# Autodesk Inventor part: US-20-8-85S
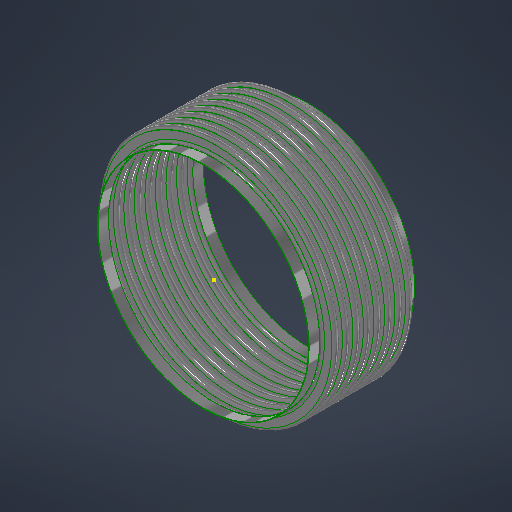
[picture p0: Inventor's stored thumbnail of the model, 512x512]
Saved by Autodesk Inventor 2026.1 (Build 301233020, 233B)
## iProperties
Category: 18 GA (0.048 THICK)
RuleStatus: InUse
Created: 2026-07
Part Number: US-20-8-85S
Project: =STOCK BELLOWS: <Stock Number><SFILL>
Material: ASTM A240-304
Description: =STOCK BELLOWS: <Stock Number>, <SID_> I.D., <SOD_> O.D., <SPLY_> PLY, <Category>, <SNET_CONS> CONS.<PITCH_><STANGENT_> TANGENT<SFILL>
Document SubType Name: Sheet Metal
Designer: LC
Stock Number: U.S-20-8-85S
Surface Area: 659.127 cm^2
Volume: 56.61 cm^3
Sheet Metal Rule: Default
Appearance: STAINLESS STEEL
NET_TUBE: 3.428
COUNTER: 1.500
PBAR: 1.214
PSET: 5.356
PLY: 2
CONS: 2
THK: 0.036
ID: 4.500
OD: 5.500
CONS_: 2
TANGENT: 0.500
PITCH: 0.375
BELLOWS_UPSET: 0.000
NET_CONS: 2
S_CONS: 0
Description_Units: 0
ID_M: 114.30 mm
OD_M: 139.70 mm
THK_M: 0.91 mm
ID_U: 4.500 in
OD_U: 5.500 in
THK_U: 0.036 in
TANGENT2: 0.500
d79: 1.000
d82: 1.000
d83: 26.000
d84: 24.000
d80: 2.571
d81: 10
SID: 2.375
SCONS_: 8
SPITCH: 0.250
SBELLOWS_UPSET: 0.000
SNET_CONS: 8
SS_CONS: 0
SCONS: 8
d174: 8
d177: 0.018
d178: 2.375
d179: 3.000
d180: 0.375
d181: 1.000
d182: 0.000
d190: 8
d191: 1
d192: 1
d193: 8
d194: 0
PART_NUMBER: U.S-20-8-85S
PRESSURE: 85
SIZE: 20.00
STANGENT_: 1.000
d214: 8
d217: 0.030
d218: 6.625
d219: 8.125
d220: 0.500
d221: 1.000
d222: 0.000
d230: 8
d231: 1
d232: 1
d233: 8
d234: 0
STANGENT: 4.000
SPLY_: 1
STHK_: 0.048
SID_: 20.000
SOD_: 22.500
SPITCH_: 1.000
STANGENT__: 1.000
SBELLOWS_UPSET_: 0.000
SDIFF_TAN: 1.000
TAN_TO_TAN: 0.750 in
d252: 2
d275: 2
d287: 0.050
d289: 0.500
d290: 0.000
d263: 2
d265: 1
d268: 2
d269: 0
d286: 2
d288: 1
d291: 2
d292: 0
SOD_NECK: 20 1/8
CFILL: .
SFILL: .
PITCH_: =, <SPITCH_> PITCH,
SREROLL: 0.750
MATTABLE: 20 GA (0.036 THICK)
MESH: ,
CSECT: 2
Author: LC
Keywords: 20 GA (0.036 THICK)
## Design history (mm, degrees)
sketch "Sketch2"
  geometry: L1 (0, -183.595)-(0, 600.956) reference; L2 (58.979, 0)-(57.15, 0); L3 (60.446, -1.467)-(66.554, -1.467); L4 (60.446, -3.296)-(66.554, -3.296); L5 (66.554, -8.058)-(60.446, -8.058); L6 (66.554, -6.229)-(60.446, -6.229); L7 (58.979, -9.525)-(57.15, -9.525); L8 (60.446, 0)-(60.446, -9.525); L9 (66.554, -4.762)-(69.85, -4.763); L10 (57.15, 0)-(57.15, -9.525); L11 (20.376, 102.841)-(20.376, 101.926); L12 (58.262, 488.877)-(58.262, 349.177); L13 (58.262, 479.352)-(58.262, 339.652); L14 (93.133, -58.817)-(93.133, -71.517); L15 (118.746, -66.401)-(118.746, -66.401); L16 (66.554, -6.229)-(66.554, -8.058); L17 (60.446, -6.229)-(60.446, -8.058); L18 (60.446, -7.144)-(66.554, -7.144); L19 (69.85, 0)-(69.85, -9.525); L20 (-66.554, -6.229)-(-66.554, -8.058); L21 (-66.554, -1.467)-(-60.446, -1.467); L22 (-66.554, -3.296)-(-60.446, -3.296); L23 (-60.446, -6.229)-(-66.554, -6.229); L24 (-66.554, -7.144)-(-60.446, -7.144); L25 (-60.446, -8.058)-(-66.554, -8.058); L26 (-60.446, -6.229)-(-60.446, -8.058); L27 (-57.15, -2.522)-(-57.15, -12.047); L28 (-60.446, -4.763)-(-57.15, -4.763); L29 (-66.554, 3.828)-(-66.554, -9.525); L30 (-68.021, 0)-(-69.85, 0); L31 (-69.85, 0)-(-69.85, -9.525); L32 (-68.021, -9.525)-(-69.85, -9.525); A1 r 1.467 centre (60.446, 0) between (58.979, 0) and (60.446, -1.467); A2 r 3.296 centre (60.446, 0) between (57.15, 0) and (60.446, -3.296); A3 r 3.296 centre (66.554, -4.762) between (66.554, -8.058) and (66.554, -1.467); A4 r 1.467 centre (66.554, -4.762) between (66.554, -6.229) and (66.554, -3.296); A5 r 1.467 centre (60.446, -9.525) between (60.446, -8.058) and (58.979, -9.525); A6 r 3.296 centre (60.446, -9.525) between (60.446, -6.229) and (57.15, -9.525); A7 r 2.381 centre (66.554, -4.762) between (66.554, -7.144) and (68.936, -4.762); A8 r 2.381 centre (60.446, -9.525) between (60.446, -7.144) and (58.064, -9.525); A9 r 1.467 centre (-66.554, -9.525) between (-66.554, -8.058) and (-68.021, -9.525); A10 r 1.467 centre (-60.446, -4.763) between (-60.446, -6.229) and (-60.446, -3.296); A11 r 2.381 centre (-60.446, -4.763) between (-60.446, -7.144) and (-58.064, -4.763); A12 r 3.296 centre (-60.446, -4.763) between (-60.446, -8.058) and (-60.446, -1.467); A13 r 2.381 centre (-66.554, -9.525) between (-66.554, -7.144) and (-68.936, -9.525); A14 r 3.296 centre (-66.554, -9.525) between (-66.554, -6.229) and (-69.85, -9.525); A15 r 1.467 centre (-66.554, 0) between (-68.021, 0) and (-66.554, -1.467); A16 r 3.296 centre (-66.554, 0) between (-69.85, 0) and (-66.554, -3.296); 10 further points
  constraints: 62 end point, 38 point on circle, 20 tangent, 16 centre point, 12 parallel, 9 midpoint, 7 vertical, 6 coincident, 6 concentric, 6 point on line, 4 equal radius, 4 perpendicular, 3 horizontal, 1 collinear, 1 horizontal alignment, 10 other
  dimensions: "THK" = 0.9144 distance of L11.start L11.end; "ID" = 114.3 distance of L11.end point (20.376, -12.374); "OD" = 139.7 distance of L12.start L12.end; "PITCH" = 9.525 distance of L12.start L13.start; "TANGENT" = 12.7 distance of L14.start L14.end; "BELLOWS_UPSET" = 0 distance of L15.start L15.end; "d43" = 114.3 diameter of L10 L1 (= ID); "d44" = 139.7 diameter of L9.end L1 (= OD); "d45" = 1.8288 distance between parallel lines of L5 L6 (computed from THK, PLY); "d46" = 3.29565 radius of A3 (computed from PITCH, THK, PLY); "UPSET_PITCH" = 9.525 distance of L2.end L7.end (derived); "SIDEWALL_ANGLE" = 0 deg angle of L3 L9 (derived); "CON_GAP" = 2.9337 distance of point (60.446, -6.229) point (60.446, -3.296) (derived); "TAN1" = 3.74046 dimension on A8 (derived); "TAN2" = 3.74046 dimension on A7 (derived); "LEG1" = 6.1087 distance of L18.start L18.end (derived); "d278" = 1.8288 distance between parallel lines of L25 L23 (derived); "d279" = 3.29565 radius of A12 (derived); "d280" = 9.525 distance of L30.end L31.end (derived); "d281" = 360 deg dimension on L21 L28 (derived); "d282" = 2.9337 distance of point (-66.554, -6.229) point (-66.554, -3.296) (derived); "d283" = 3.74046 dimension on A13 (derived); "d284" = 3.74046 dimension on A11 (derived); "d285" = 6.1087 distance of L24.start L24.end (derived); "d293" = 114.3 diameter of L27 L1 (derived); "d294" = 139.7 diameter of L31 L1 (derived)
  node "Sketch Rectangular Pattern1" dims "d31" = 25.4, "ID" = 114.3
  node "Sketch Rectangular Pattern2" dims "d39" = 25.4, "PITCH" = 9.525
revolve "CONS" stored, may be unused: angle "d48" = 90 deg
node "BELLOW MIDPLANE"
pattern_linear "Rectangular Pattern2" dims "d52" = 9.525 (= UPSET_PITCH)
sketch "Sketch5"
  geometry: C1 r 58.979 at (0, 0) reference; C2 r 57.15 at (0, 0) reference
extrude "TANGENT" new body sketch "Sketch5" distance "d53" = 12.7 (= TANGENT); taper "d54" = 0 deg
revolve "SAMETAN" stored, may be unused: angle "d65" = 90 deg
revolve "DIFFTAN" stored, may be unused: angle "d70" = 90 deg
sketch "Sketch9"
  geometry: L1 (58.391, 0)-(-58.391, 0) reference; L2 (0, -17.78)-(0, 17.78) reference; L3 (41.708, 0)-(-41.708, 0); L4 (41.708, -11.906)-(41.708, 11.906); L5 (29.008, -11.906)-(29.008, 11.906); L6 (15.418, 11.906)-(15.418, -11.906); L7 (-29.008, -11.906)-(-29.008, 11.906); L8 (-41.708, -11.906)-(-41.708, 11.906); L9 (40.914, -11.906)-(40.914, 11.906); L10 (41.708, -11.906)-(40.914, -11.906); L11 (41.708, 11.906)-(40.914, 11.906); L12 (15.815, 11.906)-(15.022, 11.906); L13 (15.022, 11.906)-(15.022, -11.906); L14 (15.022, -11.906)-(15.815, -11.906); L15 (15.815, -11.906)-(15.815, 11.906); L16 (-15.815, 11.906)-(-15.815, -11.906); L17 (-15.418, 11.906)-(-15.418, -11.906); L18 (-15.815, -11.906)-(-15.022, -11.906); L19 (-15.022, -11.906)-(-15.022, 11.906); L20 (-15.022, 11.906)-(-15.815, 11.906); L21 (-41.708, -11.906)-(-40.914, -11.906); L22 (-40.914, -11.906)-(-40.914, 11.906); L23 (-40.914, 11.906)-(-41.708, 11.906); L24 (-41.708, 11.906)-(-41.708, -11.906); L25 (41.708, -0.397)-(-41.708, -0.397); L26 (-41.708, -0.397)-(-41.708, 0.397); L27 (-41.708, 0.397)-(41.708, 0.397); L28 (41.708, 0.397)-(41.708, -0.397); L29 (-41.708, 11.906)-(41.708, 11.906); L30 (41.708, 11.906)-(41.708, 12.7); L31 (41.708, 12.7)-(-41.708, 12.7); L32 (-41.708, 12.7)-(-41.708, 11.906); L33 (41.708, -11.906)-(-41.708, -11.906); L34 (-41.708, -11.906)-(-41.708, -12.7); L35 (-41.708, -12.7)-(41.708, -12.7); L36 (41.708, -12.7)-(41.708, -11.906); 30 further points
  constraints: 68 end point, 13 midpoint, 13 parallel, 8 horizontal, 7 perpendicular, 6 equal length, 3 point on line, 2 vertical, 14 other
  dimensions: "d115" = 23.8125 distance of L4.start L4.end (derived); "d116" = 12.7 distance between parallel lines of L4 L5 (derived); "d117" = 13.58962 distance between parallel lines of L5 L6 (derived); "d125" = 44.42645 distance between parallel lines of L7 L6 (derived); "d127" = 12.7 distance between parallel lines of L8 L7 (derived); "d128" = 26.28962 distance between parallel lines of L6 L4 (derived); "d130" = 83.41607 distance between parallel lines of L8 L4 (derived); "RULER_THK" = 0.79375 distance between parallel lines of L4 L9; "d135" = 0.79375 distance of L13.end L14.end (derived); "d138" = 30.83684 distance of L13.end L16.end (derived); "d143" = 0.79375 distance of L22.end L8.end (derived); "d144" = 0.79375 distance between parallel lines of L27 L25 (derived)
extrude "RULER" join sketch "Sketch9" distance "d149" = 0.79375 (derived); taper "d150" = 0 deg
extrude "BARS" join sketch "Sketch9" distance "d151" = 0.79375 (derived); taper "d152" = 0 deg
pattern_linear "Rectangular Pattern4" dims "d155" = 30.83684 (derived)
sketch "Sketch13"
  geometry: L1 (93.149, -52.467)-(93.149, -77.867); L2 (255.219, 0)-(254, 0); L3 (255.219, -25.4)-(254, -25.4); L4 (278.79, -19.66)-(260.96, -19.66); L5 (278.79, -18.44)-(260.96, -18.44); L6 (278.79, -12.7)-(285.75, -12.7); L7 (260.96, -5.74)-(278.79, -5.74); L8 (260.96, 0)-(260.96, -25.4); L9 (254, 0)-(254, -25.4); L10 (58.254, -203.273)-(58.254, -774.773); L11 (58.254, -228.673)-(58.254, -800.173); L12 (58.254, -279.473)-(58.254, -850.973); L13 (58.254, -304.873)-(58.254, -876.373); L14 (58.254, -330.273)-(58.254, -901.773); L15 (58.254, -355.673)-(58.254, -927.173); L16 (58.254, -381.073)-(58.254, -952.573); L17 (58.254, -254.073)-(58.254, -825.573); L18 (20.376, 103.145)-(20.376, 101.926); L19 (260.96, -6.96)-(278.79, -6.96); L20 (0, -1123.076)-(0, 307.516) reference; L21 (-52.07, 0)-(312.42, 0) reference; A1 r 5.74 centre (260.96, 0) between (255.219, 0) and (260.96, -5.74); A2 r 5.74 centre (260.96, -25.4) between (260.96, -19.66) and (255.219, -25.4); A3 r 6.96 centre (260.96, -25.4) between (260.96, -18.44) and (254, -25.4); A4 r 5.74 centre (278.79, -12.7) between (278.79, -18.44) and (278.79, -6.96); A5 r 6.96 centre (278.79, -12.7) between (278.79, -19.66) and (278.79, -5.74); A6 r 6.96 centre (260.96, 0) between (254, 0) and (260.96, -6.96); 6 further points; 1 other entity
  constraints: 38 end point, 15 point on circle, 9 tangent, 6 centre point, 6 parallel, 5 vertical alignment, 4 point on line, 4 vertical, 3 coincident, 3 concentric, 2 collinear, 2 equal radius, 1 horizontal, 1 perpendicular, 23 other
  dimensions: "SBELLOWS_UPSET_" = 0 distance of point (118.762, -66.401) point (118.762, -66.401); "STOTAL_THK_BELLOW__" = 1.2192 distance between parallel lines of L4 L5 (derived); "d224" = 6.9596 radius of A5 (derived); "d225" = 25.4 distance of L2.end L3.end (derived); "SSIDEWALL_ANGLE_" = 0 deg angle of L7 L6 (derived); "SSCON_GAP_" = 11.4808 distance of point (260.96, -18.44) point (260.96, -6.96) (derived); "d235" = 508 diameter of L9 L20 (derived); "d236" = 571.5 diameter of L6.end L20 (derived)
  node "Sketch Rectangular Pattern4" dims "d228" = 25.4
  node "Sketch Rectangular Pattern5" dims "d229" = 25.4
revolve "SBELLOW" stored, may be unused: angle "d197" = 90 deg
pattern_linear "Rectangular Pattern5" dims "d204" = 25.4 (derived)
revolve "STANGENT" stored, may be unused: angle "d240" = 90 deg
revolve "SSAMETAN" stored, may be unused: angle "d241" = 90 deg
revolve "SDIFFTAN" stored, may be unused: angle "d246" = 90 deg
revolve "INVCON" stored, may be unused: angle "d295" = 90 deg
pattern_linear "Rectangular Pattern6" dims "d298" = 9.525 (derived)
revolve "INVTANGENT" stored, may be unused: angle "d302" = 90 deg
revolve "INVSAMETAN" stored, may be unused: angle "d307" = 90 deg
revolve "INVDIFFTAN" stored, may be unused: angle "d312" = 90 deg
sketch "ID BELLOW MOUNT CALC"
  geometry: L1 (44.45, 0)-(38.1, 0); L2 (38.1, 0)-(38.1, 12.7); L3 (38.1, 12.7)-(44.45, 12.7); L4 (44.45, 12.7)-(44.45, 0); L5 (36.513, 12.7)-(34.684, 12.7); L6 (34.684, 12.7)-(34.684, 0); L7 (34.684, 0)-(36.513, 0); L8 (36.513, 0)-(36.513, 12.7); L9 (0, -2.54)-(0, 15.24) reference; L10 (-8.89, 0)-(53.34, 0) reference; 1 further point
  constraints: 16 end point, 5 parallel, 2 collinear, 2 horizontal, 2 perpendicular
  dimensions: "d314" = 12.7 distance of L5.end L6.end (derived); "d315" = 1.8288 distance of L5.start L5.end (derived); "IG" = 1.5875 distance between parallel lines of L2 L8; "PIPE_OD" = 88.9 diameter of L4 L9; "PIPE_WALL" = 6.35 distance of L2.end L3.end; "ID_MT_BELLOW" = 69.3674 diameter of L6 L9 (derived)
revolve "CFILL" stored, may be unused: angle "d320" = 90 deg
pattern_linear "Rectangular Pattern7" dims "d323" = 9.525 (derived)
revolve "SFILL" stored, may be unused: angle "d324" = 90 deg
pattern_linear "Rectangular Pattern8" dims "d327" = 25.4 (derived)
node "STOCK BELLOW MIDPLANE"
sketch "Sketch21"
  geometry: L1 (0, -100.013)-(0, 100.013) reference; L2 (-100.013, 0)-(100.013, 0) reference; L3 (-0.099, 71.437)-(0.099, 71.437); L4 (0.099, 71.437)-(0.099, 55.562); L5 (0.099, 55.562)-(-0.099, 55.562); L6 (-0.099, 55.562)-(-0.099, 71.437); C1 r 55.562 at (0, 0); C2 r 71.437 at (0, 0); 3 further points
  constraints: 8 end point, 2 centre point, 2 coincident, 2 parallel, 2 tangent, 1 horizontal, 1 perpendicular, 1 other
  dimensions: "d329" = 111.125 diameter of C1 (derived); "d330" = 142.875 diameter of C2 (derived); "d331" = 0.19844 distance of L3.start L3.end
extrude "CLAMSHELL" cut sketch "Sketch21" extent not by distance; stored distance "d332" = 0; taper "d333" = 0 deg
pattern_circular "Circular Pattern1" dims angle "d335" = 180 deg (derived)
node "BELLOW"
sketch "Sketch6"
  geometry: L1 (-19.05, 58.979)-(-6.35, 58.979); L2 (-6.35, 58.979)-(-6.35, 57.15); L3 (-6.35, 57.15)-(-19.05, 57.15); L4 (-19.05, 57.15)-(-19.05, 58.979); L5 (2.54, 0)-(-59.69, 0) reference; L6 (-38.1, -108.388)-(-38.1, 156.601) reference; 1 further point
  constraints: 8 end point, 2 parallel, 1 horizontal, 1 perpendicular
  dimensions: "d61" = 12.7 distance of L2.end L3.end (derived); "d62" = 1.8288 distance of L1.end L2.end (derived); "d63" = 114.3 diameter of L3 L5 (derived); "d64" = 19.05 distance between parallel lines of L4 L6 (derived)
sketch "Sketch12"
  geometry: 1 further point
sketch "Sketch14"
  geometry: L1 (-25.4, 255.219)-(0, 255.219); L2 (0, 255.219)-(0, 254); L3 (0, 254)-(-25.4, 254); L4 (-25.4, 254)-(-25.4, 255.219); L5 (5.08, 0)-(-30.48, 0) reference; L6 (0, -45.964)-(0, 275.783) reference; 1 further point
  constraints: 8 end point, 2 parallel, 1 collinear, 1 horizontal, 1 perpendicular
  dimensions: "d237" = 1.2192 distance of L3.end L1.start (derived); "d238" = 508 diameter of L3 L5 (derived); "d239" = 25.4 distance of L1.start L1.end (derived); "SOD_NECK" = 510.4384 diameter of L1 L5 (derived)
sketch "Sketch15"
  geometry: L1 (-45.964, 0)-(275.783, 0) reference; L2 (254, -203.2)-(255.219, -203.2); L3 (255.219, -203.2)-(255.219, -228.6); L4 (255.219, -228.6)-(254, -228.6); L5 (254, -228.6)-(254, -203.2); L6 (0, -276.86)-(0, 60.96) reference; 1 further point
  constraints: 8 end point, 2 parallel, 1 horizontal, 1 perpendicular
  dimensions: "d205" = 25.4 distance of L4.end L2.start (derived); "d206" = 1.2192 distance of L3.end L4.end (derived); "d207" = 508 diameter of L5 L6 (derived); "d208" = 203.2 distance between parallel lines of L1 L2 (derived)
node "TANGENT_"
node "SAME_TAN"
sketch "Sketch8"
  geometry: L1 (58.979, -19.05)-(57.15, -19.05); L2 (57.15, -19.05)-(57.15, -31.75); L3 (57.15, -31.75)-(58.979, -31.75); L4 (58.979, -31.75)-(58.979, -19.05); L5 (0, -40.64)-(0, 21.59) reference; L6 (-108.388, 0)-(156.601, 0) reference; 1 further point
  constraints: 8 end point, 2 parallel, 1 horizontal, 1 perpendicular
  dimensions: "d66" = 114.3 diameter of L2 L5 (derived); "TOTAL_THK_BELLOW" = 1.8288 distance of L2.end L3.end (derived); "d68" = 19.05 distance between parallel lines of L1 L6 (derived); "d69" = 12.7 distance of L1.end L2.end (derived)
node "DIFF_TAN"
node "Sketch Rectangular Pattern3" dims "d138" = 30.83684 (derived), "d141" = 25.4
node "SBELLOW_"
node "STANGENT_"
node "SSAME_TAN"
sketch "Sketch16"
  geometry: L1 (255.219, -203.2)-(254, -203.2); L2 (254, -203.2)-(254, -228.6); L3 (254, -228.6)-(255.219, -228.6); L4 (255.219, -228.6)-(255.219, -203.2); L5 (0, -276.86)-(0, 60.96) reference; L6 (-45.964, 0)-(275.783, 0) reference; 1 further point
  constraints: 8 end point, 2 parallel, 1 horizontal, 1 perpendicular
  dimensions: "SDIFF_TAN" = 25.4 distance of L3.end L1.start; "d243" = 1.2192 distance of L2.end L3.end (derived); "d244" = 203.2 distance between parallel lines of L1 L6 (derived); "d245" = 508 diameter of L2 L5 (derived)
node "SDIFF_TAN"
body "Solid15"
sketch "Sketch17"
  geometry: L1 (69.85, 12.7)-(68.021, 12.7); L2 (68.021, 12.7)-(68.021, 0); L3 (68.021, 0)-(69.85, 0); L4 (69.85, 0)-(69.85, 12.7); L5 (0, -2.54)-(0, 15.24) reference; L6 (-13.97, 0)-(83.82, 0) reference; 2 further points
  constraints: 8 end point, 2 parallel, 1 horizontal, 1 midpoint, 1 perpendicular, 1 point on line
  dimensions: "INVTANGENT" = 12.7 distance of L3.end L1.start (derived); "d300" = 1.8288 distance of L1.start L1.end (derived); "d301" = 139.7 diameter of L4 L5 (derived)
body "Solid16"
sketch "Sketch18"
  geometry: L1 (69.85, -19.05)-(68.021, -19.05); L2 (68.021, -19.05)-(68.021, -31.75); L3 (68.021, -31.75)-(69.85, -31.75); L4 (69.85, -31.75)-(69.85, -19.05); L5 (-13.97, 0)-(83.82, 0) reference; L6 (0, -40.64)-(0, 21.59) reference; 1 further point
  constraints: 8 end point, 2 parallel, 1 horizontal, 1 perpendicular
  dimensions: "d303" = 19.05 distance between parallel lines of L1 L5 (derived); "d304" = 12.7 distance of L3.end L1.start (derived); "d305" = 1.8288 distance of L2.end L3.end (derived); "d306" = 139.7 diameter of L4 L6 (derived)
body "Solid17"
sketch "Sketch19"
  geometry: L1 (69.85, -19.05)-(68.021, -19.05); L2 (68.021, -19.05)-(68.021, -31.75); L3 (68.021, -31.75)-(69.85, -31.75); L4 (69.85, -31.75)-(69.85, -19.05); L5 (0, -40.64)-(0, 21.59) reference; L6 (-13.97, 0)-(83.82, 0) reference; 1 further point
  constraints: 8 end point, 2 parallel, 1 horizontal, 1 perpendicular
  dimensions: "d308" = 12.7 distance of L1.end L2.end (derived); "d309" = 139.7 diameter of L4 L5 (derived); "d310" = 1.8288 distance of L2.end L3.end (derived); "d311" = 19.05 distance between parallel lines of L1 L6 (derived)
body "Solid18"
body "Solid19"
body "Solid20"
other parameters: "BMPL" = -101.6, "PSET" = 136.0424 (computed from OD, THK, PLY) [user parameter], "PBAR" = 30.83684 (= 0.570796 x PITCH + OD - ID) [user parameter; used in 1 equation term], "COUNTER" = 15 [user parameter], "NET_TUBE" = 87.07367 (computed from CONS_, PBAR, TANGENT) [user parameter], "S_CONS" = 0 [user parameter; used in 1 equation term], "ID_M" = 114.3 (= ID) [user parameter], "OD_M" = 139.7 (= OD) [user parameter], "THK_M" = 0.9144 (= THK) [user parameter], "ID_U" = 114.3 (= ID) [user parameter], "OD_U" = 139.7 (= OD) [user parameter], "THK_U" = 0.9144 (= THK) [user parameter], "D_UNITS" = 0 [user parameter], "TANGENT2" = 12.7 [user parameter], "TAN_TO_TAN" = 19.05 [user parameter], "OD_NECK" = 117.9576 [user parameter], "d79" = 25.4, "d80" = 65.29823 [user parameter], "d82" = 25.4, "d83" = 660.4, "d84" = 609.6, "sa_0" = 4, "FRAME_THK" = 0.79375 [user parameter], "CON_FLAT" = 13.58962 [user parameter], "SID" = 60.325 [user parameter], "SPITCH" = 6.35 [user parameter], "STANGENT_" = 25.4 [user parameter], "SBELLOWS_UPSET" = 0 [user parameter], "SS_CONS" = 0 [user parameter], "STAN_TO_TAN_" = 203.2 [user parameter], "d100" = 1.2192 [user parameter], "d191" = 25.4 [user parameter], "d194" = 0 [user parameter], "STANGENT" = 101.6 [user parameter], "d234" = 0 [user parameter], "SUPSET_PITCH_" = 25.4 [user parameter], "d269" = 0 [user parameter], "d287" = 1.27, "d289" = 12.7, "d290" = 0, "d292" = 0 [user parameter], "Thickness" = 3.048 (derived), "KFactor" = 4.4, "BendRadius" = 3.048 (derived), "BendReliefWidth" = 3.048 (derived), "BendReliefDepth" = 1.524 (derived), "CornerReliefSize" = 12.192 (derived), "SeamGap" = 0.00508, "MinimumRemnant" = 6.096 (derived), "TransitionRadius" = 3.048 (derived), "JacobiRadiusSize" = 3.048 (derived), "GapSize" = 3.048 (derived), "SREROLL" = 19.05 [user parameter], "CUR_STK_PITCH" = 25.4 [user parameter], "d328" = -101.6 (derived), "CSECTDEG" = 180 deg [user parameter]
